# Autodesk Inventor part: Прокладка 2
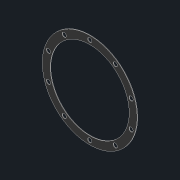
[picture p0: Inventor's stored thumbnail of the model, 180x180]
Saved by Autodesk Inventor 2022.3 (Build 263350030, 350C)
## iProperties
Created: 2022-08
Part Number: Прокладка 2
Material: Резина
Document SubType Name: Modeling
Designer: Карташов
Density: 0.93 g/cm^3
Appearance: Резина — черная
Author: Карташов
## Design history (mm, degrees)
sketch "Эскиз1"
  geometry: L1 (320, 7.5)-(320, -7.5) reference; L2 (320, 7.5)-(226.741, 7.5) reference; L3 (168, 77.353)-(168, 82.5) reference; L4 (158, 82.5)-(168, 82.5) reference; L5 (158, 82.5)-(158, 80.25) reference; L6 (118, 80.25)-(118, 82.5) reference; L7 (108, 82.5)-(118, 82.5) reference; L8 (108, 82.5)-(108, 77.353) reference; L9 (49.259, 7.5)-(28.374, 7.5) reference; L10 (-10, 55.746)-(-10, 77.5) reference; L11 (-20, 77.5)-(-10, 77.5) reference; L12 (-20, 77.5)-(-20, 59.582) reference; L13 (-60, 59.582)-(-60, 77.5) reference; L14 (-70, 77.5)-(-60, 77.5) reference; L15 (-70, 77.5)-(-70, 55.746) reference; L16 (-108.374, 7.5)-(-131.905, 7.5) reference; L17 (-185, 52.291)-(-185, 78.5) reference; L18 (-195, 78.5)-(-185, 78.5) reference; L19 (-195, 78.5)-(-195, 52.291) reference; L20 (-248.095, 7.5)-(-320, 7.5) reference; L21 (-320, -7.5)-(-320, 7.5) reference; L22 (-320, -7.5)-(-235, -7.5) reference; L23 (-145, -7.5)-(-95, -7.5) reference; L24 (15, -7.5)-(63, -7.5) reference; L25 (213, -7.5)-(320, -7.5) reference; L26 (285, -187.5)-(285, -22.5) reference; L27 (285, -187.5)-(300, -187.5) reference; L28 (300, -187.5)-(300, -22.5) reference; L29 (300, -22.5)-(320, -22.5) reference; L30 (320, -22.5)-(320, -7.5) reference; L31 (320, -7.5)-(213, -7.5) reference; L32 (63, -7.5)-(15, -7.5) reference; L33 (-95, -7.5)-(-145, -7.5) reference; L34 (-235, -7.5)-(-320, -7.5) reference; L35 (-320, -7.5)-(-320, -22.5) reference; L36 (-320, -22.5)-(-305, -22.5) reference; L37 (-300, -27.5)-(-300, -187.5) reference; L38 (-300, -187.5)-(-285, -187.5) reference; L39 (-285, -27.5)-(-285, -187.5) reference; L40 (-248.095, -22.5)-(-280, -22.5) reference; L41 (-155, -56.234)-(-154.394, -56.234) reference; L42 (-108.374, -22.5)-(-131.905, -22.5) reference; L43 (49.259, -22.5)-(28.374, -22.5) reference; L44 (285, -22.5)-(226.741, -22.5) reference; C1 r 4 at (138, 75) reference; C2 r 4 at (-3.263, 43.064) reference; C3 r 4 at (-144.534, 18.75) reference; C4 r 4 at (-235.466, 18.75) reference; C5 r 4 at (-40, 55) reference; C6 r 4 at (89.508, 59.244) reference; C7 r 4 at (186.492, 59.244) reference; C8 r 4 at (19.441, 11.814) reference; C9 r 4 at (-99.441, 11.814) reference; C10 r 4 at (-190, 45) reference; C11 r 4 at (-76.737, 43.064) reference; C12 r 4 at (59.538, 17.994) reference; C13 r 4 at (216.462, 17.994) reference; C14 r 4 at (186.492, -74.244) reference; C15 r 4 at (216.462, -32.994) reference; C16 r 4 at (59.538, -32.994) reference; C17 r 4 at (89.508, -74.244) reference; C18 r 4 at (138, -90) reference; C19 r 4 at (-3.263, -58.064) reference; C20 r 4 at (19.441, -26.814) reference; C21 r 4 at (-99.441, -26.814) reference; C22 r 4 at (-76.737, -58.064) reference; C23 r 4 at (-40, -70) reference; C24 r 4 at (-190, -60) reference; C25 r 4 at (-144.534, -33.75) reference; C26 r 4 at (-235.466, -33.75) reference; C27 r 90 at (138, -7.5); A1 r 90 centre (138, -7.5) between (226.741, 7.5) and (168, 77.353) reference; A2 r 90 centre (138, -7.5) between (158, 80.25) and (118, 80.25) reference; A3 r 90 centre (138, -7.5) between (108, 77.353) and (49.259, 7.5) reference; A4 r 70 centre (-40, -7.5) between (28.374, 7.5) and (-10, 55.746) reference; A5 r 70 centre (-40, -7.5) between (-20, 59.582) and (-60, 59.582) reference; A6 r 70 centre (-40, -7.5) between (-70, 55.746) and (-108.374, 7.5) reference; A7 r 60 centre (-190, -7.5) between (-131.905, 7.5) and (-185, 52.291) reference; A8 r 60 centre (-190, -7.5) between (-195, 52.291) and (-248.095, 7.5) reference; A9 r 45 centre (-190, -7.5) between (-145, -7.5) and (-235, -7.5) reference; A10 r 55 centre (-40, -7.5) between (15, -7.5) and (-95, -7.5) reference; A11 r 75 centre (138, -7.5) between (213, -7.5) and (63, -7.5) reference; A12 r 75 centre (138, -7.5) between (63, -7.5) and (213, -7.5) reference; A13 r 55 centre (-40, -7.5) between (-95, -7.5) and (15, -7.5) reference; A14 r 45 centre (-190, -7.5) between (-235, -7.5) and (-145, -7.5) reference; A15 r 5 centre (-305, -27.5) between (-300, -27.5) and (-305, -22.5) reference; A16 r 5 centre (-280, -27.5) between (-280, -22.5) and (-285, -27.5) reference; A17 r 60 centre (-190, -7.5) between (-248.095, -22.5) and (-225, -56.234) reference; A18 r 60 centre (-190, -7.5) between (-225, -56.234) and (-215, -62.044) reference; A19 r 60 centre (-190, -7.5) between (-215, -62.044) and (-165, -62.044) reference; A20 r 60 centre (-190, -7.5) between (-165, -62.044) and (-155, -56.234) reference; A21 r 4.5 centre (-150.5, -58.49) between (-153.256, -54.933) and (-154.394, -56.234) reference; A22 r 60 centre (-190, -7.5) between (-153.256, -54.933) and (-131.905, -22.5) reference; A23 r 70 centre (-40, -7.5) between (-108.374, -22.5) and (-75, -68.122) reference; A24 r 70 centre (-40, -7.5) between (-75, -68.122) and (-65, -72.883) reference; A25 r 70 centre (-40, -7.5) between (-65, -72.883) and (-15, -72.883) reference; A26 r 70 centre (-40, -7.5) between (-15, -72.883) and (-5, -68.122) reference; A27 r 70 centre (-40, -7.5) between (-5, -68.122) and (28.374, -22.5) reference; A28 r 90 centre (138, -7.5) between (49.259, -22.5) and (103, -90.416) reference; A29 r 90 centre (138, -7.5) between (103, -90.416) and (113, -93.958) reference; A30 r 90 centre (138, -7.5) between (113, -93.958) and (163, -93.958) reference; A31 r 90 centre (138, -7.5) between (163, -93.958) and (173, -90.416) reference; A32 r 90 centre (138, -7.5) between (173, -90.416) and (226.741, -22.5) reference; 9 further points
  constraints: 1 centre point, 1 coincident, 1 concentric
extrude "Выдавливание1" new body sketch "Эскиз1" distance "d0" = 1; taper "d1" = 0 deg
node "Твердое тело1"
node "Ссылка1"
node "Ссылка2"
